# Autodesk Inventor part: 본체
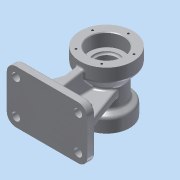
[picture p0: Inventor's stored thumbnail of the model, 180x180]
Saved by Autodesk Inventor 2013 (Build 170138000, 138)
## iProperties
Created: 2015-08
Part Number: 본체
Material: 알루미늄 6061
Document SubType Name: Modeling
Designer: Administrator
Density: 2.71 g/cm^3
Mass: 1062.55 g
Surface Area: 748.24 cm^2
Volume: 392.085 cm^3
Author: Administrator
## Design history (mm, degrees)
sketch "스케치3"
  geometry: L1 (0, 45)-(0, -45); L2 (0, 45)-(40, 45); L3 (40, 45)-(40, 25); L4 (26, 8.315)-(26, -19.804); L5 (26, -19.804)-(35, -25); L6 (35, -25)-(35, -45); L7 (35, -45)-(0, -45); L8 (26, 8.315)-(40, 25); 2 further points
  constraints: 16 end point, 3 parallel, 2 perpendicular, 1 coincident, 1 midpoint, 1 vertical
  dimensions: "d0" = 90 distance of L1.start L1.end; "d1" = 70 diameter of L6 L1; "d2" = 80 diameter of L3 L1; "d3" = 20 distance of L2.end L3.end; "d4" = 20 distance of L5.end L6.end; "d5" = 60 deg angle of L4 L5; "d6" = 40 deg angle of L4 L8; "d7" = 52 diameter of L4 L1
revolve "회전1" sketch "스케치3" stored, may be unused: angle "d8" = 90 deg
node "작업 평면1"
sketch "스케치8"
  geometry: L1 (61, -40)-(-61, -40); L2 (-61, -40)-(-61, 40); L3 (-61, 40)-(61, 40); L4 (61, 40)-(61, -40); L5 (61, -40)-(-61, 40); L6 (-61, -40)-(61, 40); 1 further point
  constraints: 12 end point, 2 midpoint, 2 parallel, 1 horizontal, 1 perpendicular
  dimensions: "d27" = 122 distance of L2.end L3.end; "d28" = 80 distance of L1.end L2.end
extrude "돌출3" join sketch "스케치8" distance "d29" = 12; taper "d30" = 0 deg
fillet "모깎기2" dims "d31" = 14
sketch "스케치9"
  geometry: L1 (6, -6)-(-6, -6); L2 (-6, -6)-(-6, 6); L3 (-6, 6)-(6, 6); L4 (6, 6)-(6, -6); L5 (6, -6)-(-6, 6); L6 (-6, -6)-(6, 6); 1 further point
  constraints: 12 end point, 2 midpoint, 2 parallel, 1 horizontal, 1 perpendicular
  dimensions: "d32" = 12 distance of L2.end L3.end; "d33" = 12 distance of L1.end L2.end
extrude "돌출4" join sketch "스케치9" stored distance "d34" = 12; taper "d35" = 0 deg
sketch "스케치10"
  geometry: L1 (61, -90)-(-61, -90) reference; L2 (-61, -90)-(-61, -78) reference; L3 (-61, -78)-(-6, -78) reference; L4 (-6, -78)-(-6, -25.298) reference; L5 (6, -25.298)-(6, -78) reference; L6 (6, -78)-(61, -78) reference; L7 (61, -78)-(61, -90) reference; L8 (25.091, -6.815)-(51, -78); A1 r 26 centre (0, 0) between (6, -25.298) and (-6, -25.298) reference; 1 further point
  constraints: 2 end point, 1 point on circle, 1 point on line
  dimensions: "d36" = 10 distance from line of L7 L8.end; "d37" = 70 deg angle of L6 L8
feature "리브2" sketch "스케치10" dims "d38" = 1, "d39" = 12, "d40" = 0, "d41" = 0, "d42" = 1, "d43" = 1
sketch "스케치11"
  geometry: L1 (-40, 45)-(40, 45) reference; L2 (40, 45)-(40, 25) reference; L3 (40, 25)-(26, 8.315) reference; L4 (26, 8.315)-(26, -19.804) reference; L5 (26, -19.804)-(35, -25) reference; L6 (35, -25)-(35, -45) reference; L7 (35, -45)-(-35, -45) reference; L8 (-35, -45)-(-35, -25) reference; L9 (-35, -25)-(-26, -19.804) reference; L10 (-26, -19.804)-(-26, -6) reference; L11 (-26, -6)-(-78, -6) reference; L12 (-78, -6)-(-78, -40) reference; L13 (-78, -40)-(-90, -40) reference; L14 (-90, -40)-(-90, 40) reference; L15 (-90, 40)-(-78, 40) reference; L16 (-78, 40)-(-78, 6) reference; L17 (-78, 6)-(-26, 6) reference; L18 (-26, 6)-(-26, 8.315) reference; L19 (-26, 8.315)-(-40, 25) reference; L20 (-40, 25)-(-40, 45) reference; L21 (-35, -30)-(-78, -30); 1 further point
  constraints: 2 end point, 2 point on line, 1 perpendicular
  dimensions: "d44" = 10 distance from line of L13 L21.end
feature "리브3" sketch "스케치11" dims "d45" = 1, "d46" = 12, "d47" = 0, "d48" = 0, "d49" = 1, "d50" = 1
sketch "스케치12"
  geometry: L1 (-40, 45)-(40, 45) reference; L2 (40, 45)-(40, 25) reference; L3 (40, 25)-(26, 8.315) reference; L4 (26, 8.315)-(26, -19.804) reference; L5 (26, -19.804)-(35, -25) reference; L6 (35, -25)-(35, -45) reference; L7 (35, -45)-(-35, -45) reference; L8 (-35, -45)-(-35, -30) reference; L9 (-35, -30)-(-78, -30) reference; L10 (-78, -30)-(-78, -40) reference; L11 (-78, -40)-(-90, -40) reference; L12 (-90, -40)-(-90, 40) reference; L13 (-90, 40)-(-78, 40) reference; L14 (-78, 40)-(-78, 6) reference; L15 (-78, 6)-(-26, 6) reference; L16 (-26, 6)-(-26, 8.315) reference; L17 (-26, 8.315)-(-40, 25) reference; L18 (-40, 25)-(-40, 45) reference; L19 (-40, 36.7)-(-78, 30); 1 further point
  constraints: 2 end point, 2 point on line
  dimensions: "d51" = 10 distance from line of L19.end L13; "d52" = 80 deg angle of L14 L19
feature "리브4" sketch "스케치12" dims "d53" = 1, "d54" = 12, "d55" = 0, "d56" = 0, "d57" = 1, "d58" = 1
hole "구멍1" diameter "d61" = 38; stored, may be unused: countersink angle "d65" = 90 deg, drill point angle "d67" = 0 deg; dims "d59" = 10, "d60" = 10, "d62" = 6, "d63" = 52, "d64" = 20, "d66" = 23
hole "구멍2" diameter "d70" = 32; stored, may be unused: countersink angle "d74" = 90 deg, drill point angle "d76" = 118 deg; dims "d68" = 10, "d69" = 10, "d71" = 6, "d72" = 40, "d73" = 17, "d75" = 23
sketch "스케치13"
  geometry: C1 r 26 at (0, 0) reference; 1 further point
  constraints: 1 vertical alignment
  dimensions: "d77" = 33 distance of C1.centre point (0, 33)
hole "구멍3" sketch "스케치13" at (0, 33) diameter "d78" = 3.242; stored, may be unused: countersink angle "d82" = 90 deg, drill point angle "d84" = 118 deg; dims "d79" = 10, "d80" = 40, "d81" = 17, "d83" = 13
sketch "스케치14"
  geometry: C1 r 20 at (0, 0) reference; 1 further point
  constraints: 1 vertical alignment
  dimensions: "d88" = 27 distance of C1.centre point (0, 27)
hole "구멍4" sketch "스케치14" at (0, 27) diameter "d89" = 3.242; stored, may be unused: countersink angle "d93" = 90 deg, drill point angle "d95" = 118 deg; dims "d90" = 10, "d91" = 40, "d92" = 17, "d94" = 13
sketch "스케치15"
  geometry: L1 (33, 24)-(33, 18); L2 (21, 24)-(21, 18); L3 (98, -12)-(4, -12) reference; L4 (-10, 0)-(4, 0) reference; L5 (-10, 0)-(0, 0) reference; L6 (0, 0)-(45, 0) reference; L7 (45, 0)-(45, 52.702) reference; L8 (0, 0)-(25.909, 71.185) reference; L9 (-10, -12)-(-10, 0) reference; L10 (112, -12)-(-10, -12) reference; L11 (112, 0)-(112, -12) reference; L12 (102, 0)-(112, 0) reference; L13 (57, 0)-(102, 0) reference; L14 (57, 52.702)-(57, 0) reference; L15 (76.091, 71.185)-(102, 0) reference; C1 r 16 at (51, 78) reference; A1 r 26 centre (51, 78) between (25.909, 71.185) and (45, 52.702) reference; A2 r 6 centre (27, 24) between (33, 24) and (21, 24); A3 r 6 centre (27, 18) between (21, 18) and (33, 18); A4 r 26 centre (51, 78) between (25.909, 71.185) and (45, 52.702) reference; A5 r 26 centre (51, 78) between (57, 52.702) and (76.091, 71.185) reference; A6 r 26 centre (51, 78) between (76.091, 71.185) and (25.909, 71.185) reference
  constraints: 4 end point, 4 point on circle, 4 tangent, 2 centre point, 1 vertical alignment
  dimensions: "d99" = 12 diameter of A2; "d100" = 12 diameter of A3; "d101" = 18 dimension on A3 A2; "d103" = 18 distance from line of A3.centre L4; "d104" = 24 horizontal distance of A1.centre A3.centre
extrude "돌출5" cut sketch "스케치15" stored distance "d105" = 10; taper "d106" = 0 deg
fillet "모깎기3" dims "d107" = 3
fillet "모깎기4" dims "d108" = 5
fillet "모깎기5" dims "d109" = 0.3
fillet "모깎기6" dims "d110" = 3
sketch "스케치16"
  geometry: C1 r 6 at (-47, 26); C2 r 6 at (47, 26); C3 r 6 at (-47, -26); C4 r 6 at (47, -26); A1 r 14 centre (-47, 26) between (-47, 40) and (-61, 26) reference; A2 r 14 centre (-47, -26) between (-61, -26) and (-47, -40) reference; A3 r 14 centre (47, -26) between (47, -40) and (61, -26) reference; A4 r 14 centre (47, 26) between (61, 26) and (47, 40) reference; 1 further point
  constraints: 4 centre point, 4 coincident
  dimensions: "d111" = 12 diameter of C1; "d112" = 12 diameter of C2; "d113" = 12 diameter of C3; "d114" = 12 diameter of C4
extrude "돌출6" cut sketch "스케치16" stored distance "d115" = 10; taper "d116" = 0 deg
fillet "모깎기7" dims "d117" = 3
sketch "스케치17"
  geometry: L1 (35, -15)-(-17, -15) reference; L2 (-28, -3)-(-17, -3) reference; L3 (-21, 37.119)-(-21, 0) reference; 2 further points
  constraints: 1 other
  dimensions: "d119" = 24 distance from line of point (-5, 21) L2; "d120" = 16 distance from line of L3 point (-5, 21)
feature "엠보싱1" sketch "스케치17" dims "d121" = 0.5, "d122" = 0
chamfer "모따기1" distance "d123" = 1; stored, may be unused: second distance "d124" = 2, angle "d125" = 45 deg
node "솔리드1"
mirror "대칭2"
pattern_circular "원형 패턴1" dims angle "d86" = 360 deg
pattern_circular "원형 패턴2" dims angle "d97" = 360 deg
mirror "대칭3"
node "절단 모서리 투영3"
node "절단 모서리 투영4"
node "절단 모서리 투영5"
node "절단 모서리 투영6"
